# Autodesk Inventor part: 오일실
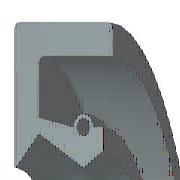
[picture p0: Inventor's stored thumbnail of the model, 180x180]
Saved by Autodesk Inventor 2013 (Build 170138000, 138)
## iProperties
IsCustomPart: 0
Manager: KYOUNG IL JANG
Company: 한국ATC센터
Created: 2009-02
Part Number: 오일실
Material: 고무
Description: 오일-실
Document SubType Name: Modeling
Standard: KS B 2804
Standards Organization: KS
Language: ko-KR
Size Designation: D - 20 35 8
Categories: <MemberInstance><Categories><Category DisplayName="샤프트 부품" InternalName="7f7aeb1f-a693-4053-b835-cee3144e0d98" Mnemonic="SHFT"><Category DisplayName="실링" Intern
Density: 0.93 g/cm^3
Checked By: KYOUNG IL JANG
Vendor: CBT Solutions
Designer: KYOUNG IL JANG
Author: KYOUNG IL JANG
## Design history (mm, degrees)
revolve "본체" stored, may be unused: angle "d17" = 90 deg
revolve "스프링1" stored, may be unused: angle "d18" = 90 deg
body "Solid1"
sketch "스케치1"
  geometry: L1 (0, 17.5)-(8, 17.5); L2 (8, 15.75)-(1.75, 15.75); L3 (1.75, 11.75)-(4.9, 10); L4 (4.9, 10)-(0, 10); L5 (0, 0)-(9.586, 0) reference; L6 (4.9, 10)-(6.3, 10.875); L7 (0, 18)-(0, -3) reference; L8 (-1.941, 0)-(11.507, 0) reference; L9 (4.2, 12.1)-(1.75, 12.71); L10 (1.75, 12.71)-(1.75, 15.75); L11 (0, 17.5)-(0, 10.088); L12 (4.9, 10)-(0, 10); L13 (1.75, 11.75)-(0.152, 10.028); L14 (8, 17.5)-(8, 15.75); L15 (5.6, 12.1)-(6.3, 12.1); L16 (6.3, 12.1)-(6.3, 10.875); C1 r 0.455 at (4.9, 12.1); A1 r 0.7 centre (4.9, 12.1) between (5.6, 12.1) and (4.2, 12.1); A2 r 0.088 centre (0.088, 10.088) between (0, 10.088) and (0.152, 10.028); 1 further point
  constraints: 28 end point, 5 horizontal alignment, 5 point on line, 4 point on circle, 4 vertical alignment, 3 centre point, 3 tangent, 2 collinear, 2 horizontal, 2 perpendicular, 1 coincident, 1 parallel
  dimensions: "d0" = 35 diameter of L1 L5 (= SD2); "d1" = 1.75 distance of L1.end L2.start (= SD); "d2" = 0.91 diameter of C1 (= SPDI); "d3" = 1.4 diameter of A1 (= SPDA); "d4" = 20 diameter of L3.end L5 (= NND); "d5" = 23.5 diameter of L3.start L5 (= TKDM); "d7" = 25.42 diameter of L9.end L5 (= TKDM + 0.24 x SWDT); "d8" = 1.75 distance between parallel lines of L11 L10 (= SD); "d9" = 4.9 distance from line of L11 C1.centre (= SPDST); "d10" = 24.2 diameter of C1.centre L5 (= HLDM); "d11" = 0.0875 radius of A2 (= 0.25 x LAB); "d12" = 6.3 distance between parallel lines of L11 L16 (= SDI); "d13" = 21.75 diameter of L6.end L5 (= ABDM); "d14" = 8 distance from line of L11 L1.end (= SWDT)
fillet "모깎기1" dims "d6" = 0.3 (= RR)
other parameters: "SD2" = 35 [user parameter; used in 1 equation term], "SWDT" = 8 [user parameter; used in 2 equation terms], "RR" = 0.3 [user parameter; used in 1 equation term], "SD" = 1.75 [user parameter; used in 2 equation terms], "NND" = 20 [user parameter; used in 1 equation term], "SPDA" = 1.4 [user parameter; used in 1 equation term], "SPDI" = 0.91 [user parameter; used in 1 equation term], "TKDM" = 23.5 [user parameter; used in 2 equation terms], "HLDM" = 24.2 [user parameter; used in 1 equation term], "ABDM" = 21.75 [user parameter; used in 1 equation term], "SDI" = 6.3 [user parameter; used in 1 equation term], "SPDST" = 4.9 [user parameter; used in 1 equation term], "LAB" = 0.35 [user parameter; used in 1 equation term], "d15" = 0, "d16" = 0, "d19" = 0
